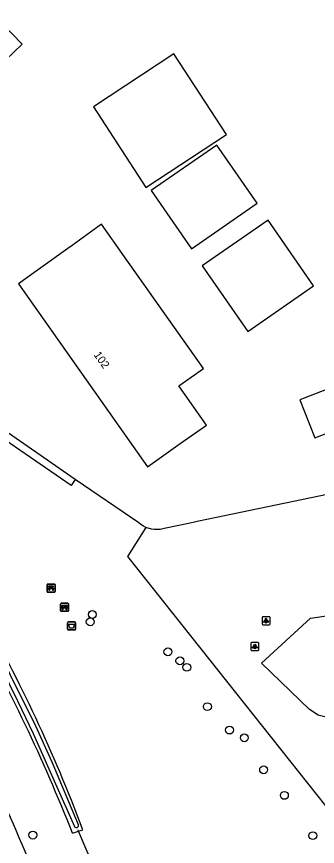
# Model space of a CAD drawing. Extents: x 152881 to 155736, y 382924 to 386919.
# Drawn here: x 152953.1 to 152990.7, y 384870.4 to 384974.1 of the extents above; entities that cross this region are included whole.
import ezdxf

# ---------------------------------------------------------------- set-up
doc = ezdxf.new("R2010")
doc.units = 0
for name, color, linetype in [('IMGEO_Afvalbak', 7, 'Continuous'), ('IMGEO_Bank', 7, 'Continuous'), ('IMGEO_Boom', 7, 'Continuous'), ('IMGEO_Duiker', 7, 'Continuous'), ('IMGEO_Fietspad_gesloten', 7, 'Continuous'), ('IMGEO_Groenvoorziening', 7, 'Continuous'), ('IMGEO_Lichtpunt', 7, 'Continuous'), ('IMGEO_Pand', 7, 'Continuous'), ('IMGEO_Pand_nummerreeks', 7, 'Continuous'), ('IMGEO_Rijbaan_lokaal_gesloten', 7, 'Continuous'), ('IMGEO_Rijbaan_lokaal_open', 7, 'Continuous'), ('IMGEO_Voetpad_open', 7, 'Continuous'), ('IMGEO_Waterloop', 7, 'Continuous')]:
    doc.layers.add(name, color=color, linetype=linetype)

msp = doc.modelspace()

# ---------------------------------------------------------------- linework, layer by layer
at = {"layer": 'IMGEO_Afvalbak'}
for p, q in [((152959.52, 384897.57), (152959.52, 384898.37)), ((152959.52, 384898.37), (152959.52, 384897.57)), ((152959.62, 384898.47), (152960.41, 384898.47)), ((152960.41, 384898.47), (152959.62, 384898.47)), ((152960.51, 384898.37), (152960.51, 384897.57)), ((152960.51, 384897.57), (152960.51, 384898.37)), ((152960.41, 384897.47), (152959.62, 384897.47)), ((152959.62, 384897.47), (152960.41, 384897.47))]:
    msp.add_line(p, q, dxfattribs=at)
msp.add_lwpolyline([(152959.66, 384898.18), (152960.37, 384898.18), (152960.22, 384897.71), (152959.81, 384897.71), (152959.66, 384898.18)], dxfattribs=at)
for centre, start, end in [((152959.62, 384898.37), 90, 180), ((152959.62, 384898.37), 90, 180), ((152960.41, 384898.37), 0, 90), ((152960.41, 384898.37), 360, 90), ((152959.62, 384897.57), 180, 270), ((152959.62, 384897.57), 180, 270), ((152960.41, 384897.57), 270, 0), ((152960.41, 384897.57), 270, 0)]:
    msp.add_arc(centre, 0.1, start, end, dxfattribs=at)
at = {"layer": 'IMGEO_Bank'}
for p, q in [((152956.95, 384902.27), (152956.95, 384903.11)), ((152956.95, 384903.11), (152956.95, 384902.27)), ((152957.02, 384903.19), (152957.86, 384903.19)), ((152957.86, 384903.19), (152957.02, 384903.19)), ((152957.95, 384903.12), (152957.95, 384902.28)), ((152957.95, 384902.28), (152957.95, 384903.12)), ((152957.87, 384902.2), (152957.03, 384902.2)), ((152957.03, 384902.2), (152957.87, 384902.2)), ((152957.64, 384902.59), (152957.25, 384902.59)), ((152957.26, 384902.7), (152957.26, 384902.81)), ((152957.3, 384902.81), (152957.3, 384902.7)), ((152957.59, 384902.81), (152957.31, 384902.81)), ((152957.31, 384902.7), (152957.59, 384902.7)), ((152957.59, 384902.7), (152957.59, 384902.81)), ((152957.64, 384902.81), (152957.64, 384902.7)), ((152958.63, 384899.87), (152958.63, 384900.71)), ((152958.63, 384900.71), (152958.63, 384899.87)), ((152958.7, 384900.8), (152959.54, 384900.8)), ((152959.54, 384900.8), (152958.7, 384900.8)), ((152959.32, 384900.2), (152958.93, 384900.2)), ((152958.94, 384900.3), (152958.94, 384900.41)), ((152958.98, 384900.41), (152958.98, 384900.3)), ((152959.27, 384900.42), (152958.99, 384900.42)), ((152958.99, 384900.3), (152959.27, 384900.3)), ((152959.27, 384900.3), (152959.27, 384900.41)), ((152959.32, 384900.41), (152959.32, 384900.3)), ((152959.63, 384900.72), (152959.63, 384899.88)), ((152959.63, 384899.88), (152959.63, 384900.72)), ((152959.55, 384899.8), (152958.71, 384899.8)), ((152958.71, 384899.8), (152959.55, 384899.8))]:
    msp.add_line(p, q, dxfattribs=at)
for points in [[(152957.25, 384902.81), (152957.16, 384902.81), (152957.16, 384902.97), (152957.73, 384902.97), (152957.73, 384902.81), (152957.64, 384902.81)], [(152957.19, 384902.59), (152957.05, 384902.59), (152957.16, 384902.7), (152957.25, 384902.7)], [(152957.24, 384902.59), (152957.24, 384902.38), (152957.2, 384902.38), (152957.2, 384902.59)], [(152957.64, 384902.7), (152957.73, 384902.7), (152957.84, 384902.59), (152957.7, 384902.59)], [(152957.69, 384902.59), (152957.69, 384902.38), (152957.65, 384902.38), (152957.65, 384902.59)], [(152958.87, 384900.2), (152958.73, 384900.2), (152958.84, 384900.3), (152958.93, 384900.3)], [(152958.93, 384900.42), (152958.84, 384900.42), (152958.84, 384900.58), (152959.41, 384900.58), (152959.41, 384900.42), (152959.32, 384900.42)], [(152958.92, 384900.19), (152958.92, 384899.98), (152958.88, 384899.98), (152958.88, 384900.19)], [(152959.32, 384900.3), (152959.41, 384900.3), (152959.52, 384900.2), (152959.38, 384900.2)], [(152959.37, 384900.19), (152959.37, 384899.98), (152959.33, 384899.98), (152959.33, 384900.19)]]:
    msp.add_lwpolyline(points, dxfattribs=at)
for centre, radius, start, end in [((152957.02, 384903.12), 0.0779, 92.4484, 184.2845), ((152957.02, 384903.12), 0.0779, 92.4484, 184.2845), ((152957.87, 384903.12), 0.0779, 2.4484, 94.2845), ((152957.87, 384903.12), 0.0779, 2.4484, 94.2845), ((152957.02, 384902.27), 0.0779, 182.4484, 274.2845), ((152957.02, 384902.27), 0.0779, 182.4484, 274.2845), ((152957.19, 384902.59), 0.00671, 2.8957, 87.1043), ((152957.25, 384902.59), 0.00671, 92.8957, 177.1043), ((152957.25, 384902.81), 0.00671, 2.8957, 87.1043), ((152957.25, 384902.7), 0.00671, 272.8957, 357.1043), ((152957.31, 384902.81), 0.00671, 92.8957, 177.1043), ((152957.31, 384902.7), 0.00671, 182.8957, 267.1043), ((152957.59, 384902.81), 0.00671, 2.8957, 87.1043), ((152957.59, 384902.7), 0.00671, 272.8957, 357.1043), ((152957.64, 384902.81), 0.00671, 92.8957, 177.1043), ((152957.64, 384902.7), 0.00671, 182.8957, 267.1043), ((152957.64, 384902.59), 0.00671, 2.8957, 87.1043), ((152957.7, 384902.59), 0.00671, 92.8957, 177.1043), ((152957.87, 384902.27), 0.0779, 272.4484, 4.2845), ((152957.87, 384902.27), 0.0779, 272.4484, 4.2845), ((152958.71, 384900.72), 0.0779, 92.4484, 184.2845), ((152958.71, 384900.72), 0.0779, 92.4484, 184.2845), ((152958.71, 384899.88), 0.0779, 182.4484, 274.2845), ((152958.71, 384899.88), 0.0779, 182.4484, 274.2845), ((152958.87, 384900.19), 0.00671, 2.8957, 87.1043), ((152958.93, 384900.19), 0.00671, 92.8957, 177.1043), ((152958.93, 384900.41), 0.00671, 2.8957, 87.1043), ((152958.93, 384900.3), 0.00671, 272.8957, 357.1043), ((152958.99, 384900.41), 0.00671, 92.8957, 177.1043), ((152958.99, 384900.3), 0.00671, 182.8957, 267.1043), ((152959.27, 384900.41), 0.00671, 2.8957, 87.1043), ((152959.27, 384900.3), 0.00671, 272.8957, 357.1043), ((152959.32, 384900.41), 0.00671, 92.8957, 177.1043), ((152959.32, 384900.3), 0.00671, 182.8957, 267.1043), ((152959.32, 384900.19), 0.00671, 2.8957, 87.1043), ((152959.38, 384900.19), 0.00671, 92.8957, 177.1043), ((152959.55, 384900.72), 0.0779, 2.4484, 94.2845), ((152959.55, 384900.72), 0.0779, 2.4484, 94.2845), ((152959.55, 384899.88), 0.0779, 272.4484, 4.2845), ((152959.55, 384899.88), 0.0779, 272.4484, 4.2845)]:
    msp.add_arc(centre, radius, start, end, dxfattribs=at)
at = {"layer": 'IMGEO_Boom'}
for centre in [(152962.61, 384899.4), (152962.34, 384898.48), (152972.05, 384894.74), (152973.55, 384893.61), (152974.41, 384892.8), (152976.99, 384887.89), (152979.75, 384884.96), (152981.61, 384884), (152984.01, 384880), (152986.61, 384876.8), (152955.17, 384871.84), (152990.17, 384871.77)]:
    msp.add_circle(centre, 0.489, dxfattribs=at)
at = {"layer": 'IMGEO_Duiker'}
msp.add_lwpolyline([(152964.77, 384863.36), (152964.71, 384863.51), (152963.21, 384866.94), (152961.96, 384869.81), (152960.87, 384872.32), (152960.82, 384872.49)], dxfattribs=at)
at = {"layer": 'IMGEO_Fietspad_gesloten'}
msp.add_arc((152770.16, 385151.69), 253.26, 315.4773, 319.4453, dxfattribs=at)
at = {"layer": 'IMGEO_Groenvoorziening'}
for points in [[(153014.43, 384919.05), (152978.13, 384911.5), (152975.71, 384911), (152975.22, 384910.9), (152973.41, 384910.52), (152971.6, 384910.15), (152971.42, 384910.1), (152971.07, 384910.04), (152970.71, 384910.02), (152970.35, 384910.03), (152970, 384910.08), (152969.98, 384910.08), (152969.31, 384910.29)], [(152969.31, 384910.29), (152968.99, 384910.45), (152968.68, 384910.64), (152968.4, 384910.86), (152960.45, 384916.28)], [(152969.31, 384910.29), (152967.02, 384906.65), (152998.5, 384866.99), (153000.57, 384864.33)], [(152990.81, 384886.84), (152989.76, 384887.52), (152983.74, 384893.34), (152989.86, 384898.94), (152995.03, 384899.69), (152996.36, 384899.4), (152997.58, 384898.78), (152998.6, 384897.88), (152999.35, 384896.75), (152996.39, 384890.05), (152996.07, 384888.85), (152995.39, 384887.81), (152994.42, 384887.03), (152993.25, 384886.58), (152992.01, 384886.52), (152990.81, 384886.84)], [(152960.13, 384872.08), (152960.87, 384872.32), (152961.41, 384872.49), (152961.37, 384872.6), (152961.33, 384872.71)]]:
    msp.add_lwpolyline(points, dxfattribs=at)
for centre, radius, start, end in [((152755.02, 384790.85), 220.61, 21.6036, 29.3085), ((152778.89, 384803.95), 194.97, 20.6509, 29.4288)]:
    msp.add_arc(centre, radius, start, end, dxfattribs=at)
at = {"layer": 'IMGEO_Lichtpunt'}
for p, q in [((152983.82, 384899.03), (152983.82, 384898.22)), ((152983.82, 384899.03), (152983.82, 384898.22)), ((152984.72, 384899.13), (152983.92, 384899.13)), ((152984.72, 384899.13), (152983.92, 384899.13)), ((152984.82, 384898.22), (152984.82, 384899.03)), ((152984.82, 384898.22), (152984.82, 384899.03)), ((152983.92, 384898.13), (152984.72, 384898.13)), ((152983.92, 384898.13), (152984.72, 384898.13)), ((152982.42, 384895.8), (152982.42, 384895)), ((152982.42, 384895.8), (152982.42, 384895)), ((152983.32, 384895.9), (152982.51, 384895.9)), ((152983.32, 384895.9), (152982.51, 384895.9)), ((152983.41, 384895), (152983.41, 384895.8)), ((152983.41, 384895), (152983.41, 384895.8)), ((152982.51, 384894.9), (152983.32, 384894.9)), ((152982.51, 384894.9), (152983.32, 384894.9))]:
    msp.add_line(p, q, dxfattribs=at)
for points in [[(152984.2, 384898.69), (152984.24, 384898.67), (152984.05, 384898.4), (152984.01, 384898.43), (152984.2, 384898.69)], [(152984.3, 384898.65), (152984.35, 384898.65), (152984.35, 384898.32), (152984.3, 384898.32), (152984.3, 384898.65)], [(152984.41, 384898.67), (152984.45, 384898.69), (152984.63, 384898.43), (152984.6, 384898.4), (152984.41, 384898.67)], [(152982.79, 384895.47), (152982.83, 384895.44), (152982.64, 384895.18), (152982.6, 384895.21), (152982.79, 384895.47)], [(152982.89, 384895.42), (152982.94, 384895.42), (152982.94, 384895.1), (152982.89, 384895.1), (152982.89, 384895.42)], [(152983, 384895.44), (152983.04, 384895.47), (152983.23, 384895.2), (152983.19, 384895.18), (152983, 384895.44)]]:
    msp.add_lwpolyline(points, dxfattribs=at)
for centre in [(152984.32, 384898.83), (152982.92, 384895.6)]:
    msp.add_circle(centre, 0.0994, dxfattribs=at)
for centre, start, end in [((152983.92, 384899.03), 90, 180), ((152983.92, 384899.03), 90, 180), ((152984.72, 384899.03), 0, 90), ((152984.72, 384899.03), 0, 90), ((152983.92, 384898.22), 180, 270), ((152983.92, 384898.22), 180, 270), ((152984.72, 384898.22), 270, 0), ((152984.72, 384898.22), 270, 360), ((152982.51, 384895.8), 90, 180), ((152982.51, 384895.8), 90, 180), ((152983.32, 384895.8), 0, 90), ((152983.32, 384895.8), 0, 90), ((152982.51, 384895), 180, 270), ((152982.51, 384895), 180, 270), ((152983.32, 384895), 270, 0), ((152983.32, 384895), 270, 360)]:
    msp.add_arc(centre, 0.0946, start, end, dxfattribs=at)
at = {"layer": 'IMGEO_Pand'}
for points in [[(152972.79, 384969.44), (152962.76, 384962.82), (152969.3, 384952.76), (152979.38, 384959.37), (152972.79, 384969.44)], [(152974.98, 384945.09), (152983.2, 384950.78), (152978.17, 384958.05), (152969.94, 384952.36), (152974.98, 384945.09)], [(152982.03, 384934.77), (152990.26, 384940.46), (152984.57, 384948.67), (152976.35, 384942.98), (152982.03, 384934.77)], [(152953.36, 384940.7), (152969.52, 384917.86), (152973.6, 384920.75), (152976.89, 384923.07), (152973.43, 384927.96), (152976.5, 384930.14), (152966.64, 384944.07), (152963.76, 384948.15), (152960.09, 384945.52), (152959.56, 384945.15), (152953.36, 384940.7)], [(152990.43, 384921.48), (152996.11, 384923.63), (152994.24, 384928.44), (152988.54, 384926.23), (152990.43, 384921.48)]]:
    msp.add_lwpolyline(points, dxfattribs=at)
at = {"layer": 'IMGEO_Rijbaan_lokaal_gesloten'}
msp.add_arc((152592.51, 384716.49), 392.84, 22.835, 27.1501, dxfattribs=at)
at = {"layer": 'IMGEO_Rijbaan_lokaal_open'}
msp.add_lwpolyline([(152950.03, 384970.35), (152951.75, 384968.65), (152953.83, 384970.67), (152952.59, 384971.93), (152950.69, 384973.85), (152950.73, 384974.1)], dxfattribs=at)
at = {"layer": 'IMGEO_Voetpad_open'}
for points in [[(152960.45, 384916.28), (152946.63, 384925.84)], [(152960.45, 384916.28), (152959.94, 384915.5), (152945.88, 384925.2)]]:
    msp.add_lwpolyline(points, dxfattribs=at)
at = {"layer": 'IMGEO_Waterloop'}
for points in [[(152938.16, 384914.82), (152940.11, 384911.52), (152942.35, 384908.08), (152943.83, 384905.53), (152945.75, 384902.21), (152947.99, 384898.35), (152951.21, 384892.8), (152953.24, 384888.6), (152955.2, 384884.54), (152958, 384878.23), (152960.36, 384872.9)], [(152960.89, 384873.14), (152957.57, 384880.95), (152955.56, 384885.45), (152952.34, 384891.89), (152949.33, 384897.91), (152947.27, 384901.08), (152938.71, 384915.14)]]:
    msp.add_lwpolyline(points, dxfattribs=at)
msp.add_arc((152960.6, 384873.08), 0.297, 216.3216, 12.2237, dxfattribs=at)

# ---------------------------------------------------------------- texts
at = {"layer": 'IMGEO_Pand_nummerreeks'}
msp.add_text('102', height=1, rotation=305.3112, dxfattribs=at).set_placement((152962.73, 384931.84))

doc.saveas('drawing.dxf')
